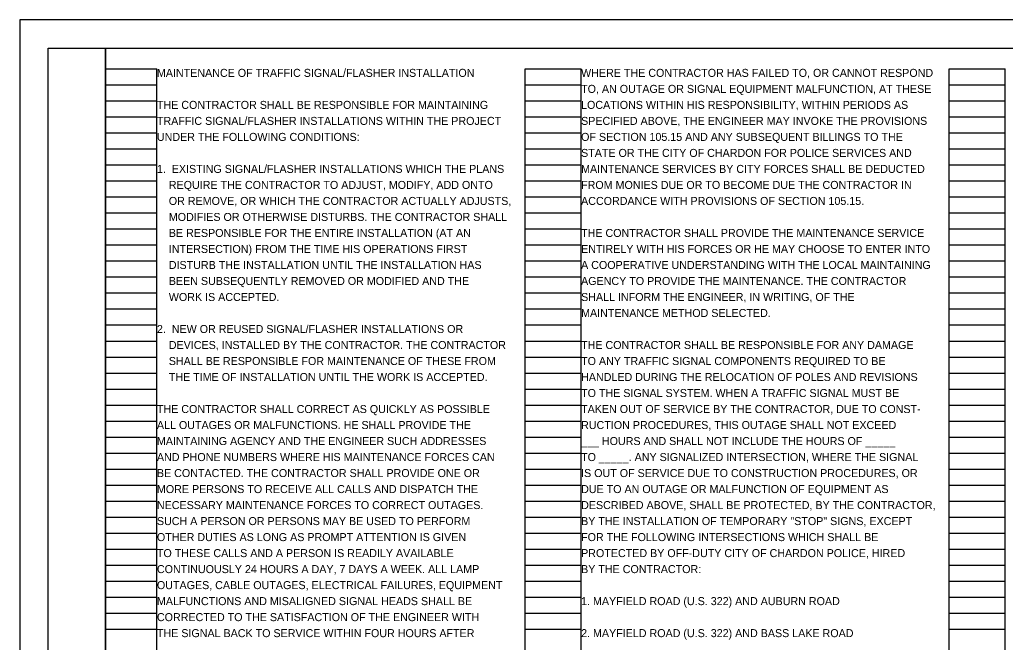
# Model space of a CAD drawing. Extents: x 0 to 63.3, y -2.5 to 22.
# Drawn here: x 0 to 17.24, y 11.11 to 22 of the extents above; entities that cross this region are included whole.
import ezdxf

# ---------------------------------------------------------------- set-up
doc = ezdxf.new("R2010")
doc.units = 0
for name, color, linetype in [('SH_Border', 7, 'Continuous'), ('SH_Cut_Line', 7, 'Continuous'), ('SH_Data', 7, 'Continuous'), ('SH_Text', 7, 'Continuous')]:
    doc.layers.add(name, color=color, linetype=linetype)

msp = doc.modelspace()

# ---------------------------------------------------------------- linework, layer by layer
at = {"layer": 'SH_Border'}
for points in [[(0.5, 21.5), (1.5, 21.5), (1.5, 0.5), (0.5, 0.5)], [(1.5, 21.5), (33.5, 21.5), (33.5, 0.5), (1.5, 0.5)]]:
    msp.add_lwpolyline(points, close=True, dxfattribs=at)
at = {"layer": 'SH_Cut_Line'}
msp.add_lwpolyline([(0, 0), (34, 0), (34, 22), (0, 22)], close=True, dxfattribs=at)
at = {"layer": 'SH_Data'}
for p, q in [((1.5, 0.98), (1.5, 21.14)), ((1.5, 21.14), (2.4, 21.14)), ((2.4, 0.98), (2.4, 21.14)), ((8.84, 0.98), (8.84, 21.14)), ((8.84, 21.14), (9.82, 21.14)), ((9.82, 0.98), (9.82, 21.14)), ((16.26, 0.98), (16.26, 21.14)), ((16.26, 21.14), (17.24, 21.14)), ((17.24, 0.98), (17.24, 21.14)), ((1.5, 20.86), (2.4, 20.86)), ((8.84, 20.86), (9.82, 20.86)), ((16.26, 20.86), (17.24, 20.86)), ((1.5, 20.58), (2.4, 20.58)), ((8.84, 20.58), (9.82, 20.58)), ((16.26, 20.58), (17.24, 20.58)), ((1.5, 20.3), (2.4, 20.3)), ((8.84, 20.3), (9.82, 20.3)), ((16.26, 20.3), (17.24, 20.3)), ((1.5, 20.02), (2.4, 20.02)), ((8.84, 20.02), (9.82, 20.02)), ((16.26, 20.02), (17.24, 20.02)), ((1.5, 19.74), (2.4, 19.74)), ((8.84, 19.74), (9.82, 19.74)), ((16.26, 19.74), (17.24, 19.74)), ((1.5, 19.46), (2.4, 19.46)), ((8.84, 19.46), (9.82, 19.46)), ((16.26, 19.46), (17.24, 19.46)), ((1.5, 19.18), (2.4, 19.18)), ((8.84, 19.18), (9.82, 19.18)), ((16.26, 19.18), (17.24, 19.18)), ((1.5, 18.9), (2.4, 18.9)), ((8.84, 18.9), (9.82, 18.9)), ((16.26, 18.9), (17.24, 18.9)), ((1.5, 18.62), (2.4, 18.62)), ((8.84, 18.62), (9.82, 18.62)), ((16.26, 18.62), (17.24, 18.62)), ((1.5, 18.34), (2.4, 18.34)), ((8.84, 18.34), (9.82, 18.34)), ((16.26, 18.34), (17.24, 18.34)), ((1.5, 18.06), (2.4, 18.06)), ((8.84, 18.06), (9.82, 18.06)), ((16.26, 18.06), (17.24, 18.06)), ((1.5, 17.78), (2.4, 17.78)), ((8.84, 17.78), (9.82, 17.78)), ((16.26, 17.78), (17.24, 17.78)), ((1.5, 17.5), (2.4, 17.5)), ((8.84, 17.5), (9.82, 17.5)), ((16.26, 17.5), (17.24, 17.5)), ((1.5, 17.22), (2.4, 17.22)), ((8.84, 17.22), (9.82, 17.22)), ((16.26, 17.22), (17.24, 17.22)), ((1.5, 16.94), (2.4, 16.94)), ((8.84, 16.94), (9.82, 16.94)), ((16.26, 16.94), (17.24, 16.94)), ((1.5, 16.66), (2.4, 16.66)), ((8.84, 16.66), (9.82, 16.66)), ((16.26, 16.66), (17.24, 16.66)), ((1.5, 16.38), (2.4, 16.38)), ((8.84, 16.38), (9.82, 16.38)), ((16.26, 16.38), (17.24, 16.38)), ((1.5, 16.1), (2.4, 16.1)), ((8.84, 16.1), (9.82, 16.1)), ((16.26, 16.1), (17.24, 16.1)), ((1.5, 15.82), (2.4, 15.82)), ((8.84, 15.82), (9.82, 15.82)), ((16.26, 15.82), (17.24, 15.82)), ((1.5, 15.54), (2.4, 15.54)), ((8.84, 15.54), (9.82, 15.54)), ((16.26, 15.54), (17.24, 15.54)), ((1.5, 15.26), (2.4, 15.26)), ((8.84, 15.26), (9.82, 15.26)), ((16.26, 15.26), (17.24, 15.26)), ((1.5, 14.98), (2.4, 14.98)), ((8.84, 14.98), (9.82, 14.98)), ((16.26, 14.98), (17.24, 14.98)), ((1.5, 14.7), (2.4, 14.7)), ((8.84, 14.7), (9.82, 14.7)), ((16.26, 14.7), (17.24, 14.7)), ((1.5, 14.42), (2.4, 14.42)), ((8.84, 14.42), (9.82, 14.42)), ((16.26, 14.42), (17.24, 14.42)), ((1.5, 14.14), (2.4, 14.14)), ((8.84, 14.14), (9.82, 14.14)), ((16.26, 14.14), (17.24, 14.14)), ((1.5, 13.86), (2.4, 13.86)), ((8.84, 13.86), (9.82, 13.86)), ((16.26, 13.86), (17.24, 13.86)), ((1.5, 13.58), (2.4, 13.58)), ((8.84, 13.58), (9.82, 13.58)), ((16.26, 13.58), (17.24, 13.58)), ((1.5, 13.3), (2.4, 13.3)), ((8.84, 13.3), (9.82, 13.3)), ((16.26, 13.3), (17.24, 13.3)), ((1.5, 13.02), (2.4, 13.02)), ((8.84, 13.02), (9.82, 13.02)), ((16.26, 13.02), (17.24, 13.02)), ((1.5, 12.74), (2.4, 12.74)), ((8.84, 12.74), (9.82, 12.74)), ((16.26, 12.74), (17.24, 12.74)), ((1.5, 12.46), (2.4, 12.46)), ((8.84, 12.46), (9.82, 12.46)), ((16.26, 12.46), (17.24, 12.46)), ((1.5, 12.18), (2.4, 12.18)), ((8.84, 12.18), (9.82, 12.18)), ((16.26, 12.18), (17.24, 12.18)), ((1.5, 11.9), (2.4, 11.9)), ((8.84, 11.9), (9.82, 11.9)), ((16.26, 11.9), (17.24, 11.9)), ((1.5, 11.62), (2.4, 11.62)), ((8.84, 11.62), (9.82, 11.62)), ((16.26, 11.62), (17.24, 11.62)), ((1.5, 11.34), (2.4, 11.34)), ((8.84, 11.34), (9.82, 11.34)), ((16.26, 11.34), (17.24, 11.34))]:
    msp.add_line(p, q, dxfattribs=at)

# ---------------------------------------------------------------- texts
at = {"layer": 'SH_Text'}
for s, p in [('MAINTENANCE OF TRAFFIC SIGNAL/FLASHER INSTALLATION', (2.4, 21)), ('WHERE THE CONTRACTOR HAS FAILED TO, OR CANNOT RESPOND', (9.82, 21)), ('TO, AN OUTAGE OR SIGNAL EQUIPMENT MALFUNCTION, AT THESE', (9.82, 20.72)), ('THE CONTRACTOR SHALL BE RESPONSIBLE FOR MAINTAINING', (2.4, 20.44)), ('LOCATIONS WITHIN HIS RESPONSIBILITY, WITHIN PERIODS AS', (9.82, 20.44)), ('TRAFFIC SIGNAL/FLASHER INSTALLATIONS WITHIN THE PROJECT', (2.4, 20.16)), ('SPECIFIED ABOVE, THE ENGINEER MAY INVOKE THE PROVISIONS', (9.82, 20.16)), ('UNDER THE FOLLOWING CONDITIONS:', (2.4, 19.88)), ('OF SECTION 105.15 AND ANY SUBSEQUENT BILLINGS TO THE', (9.82, 19.88)), ('STATE OR THE CITY OF CHARDON FOR POLICE SERVICES AND', (9.82, 19.6)), ('1.  EXISTING SIGNAL/FLASHER INSTALLATIONS WHICH THE PLANS', (2.4, 19.32)), ('MAINTENANCE SERVICES BY CITY FORCES SHALL BE DEDUCTED', (9.82, 19.32)), ('    REQUIRE THE CONTRACTOR TO ADJUST, MODIFY, ADD ONTO', (2.4, 19.04)), ('FROM MONIES DUE OR TO BECOME DUE THE CONTRACTOR IN', (9.82, 19.04)), ('    OR REMOVE, OR WHICH THE CONTRACTOR ACTUALLY ADJUSTS,', (2.4, 18.76)), ('ACCORDANCE WITH PROVISIONS OF SECTION 105.15.', (9.82, 18.76)), ('    MODIFIES OR OTHERWISE DISTURBS. THE CONTRACTOR SHALL', (2.4, 18.48)), ('    BE RESPONSIBLE FOR THE ENTIRE INSTALLATION (AT AN', (2.4, 18.2)), ('THE CONTRACTOR SHALL PROVIDE THE MAINTENANCE SERVICE', (9.82, 18.2)), ('    INTERSECTION) FROM THE TIME HIS OPERATIONS FIRST', (2.4, 17.92)), ('ENTIRELY WITH HIS FORCES OR HE MAY CHOOSE TO ENTER INTO', (9.82, 17.92)), ('    DISTURB THE INSTALLATION UNTIL THE INSTALLATION HAS', (2.4, 17.64)), ('A COOPERATIVE UNDERSTANDING WITH THE LOCAL MAINTAINING', (9.82, 17.64)), ('    BEEN SUBSEQUENTLY REMOVED OR MODIFIED AND THE', (2.4, 17.36)), ('AGENCY TO PROVIDE THE MAINTENANCE. THE CONTRACTOR', (9.82, 17.36)), ('    WORK IS ACCEPTED.', (2.4, 17.08)), ('SHALL INFORM THE ENGINEER, IN WRITING, OF THE', (9.82, 17.08)), ('MAINTENANCE METHOD SELECTED.', (9.82, 16.8)), ('2.  NEW OR REUSED SIGNAL/FLASHER INSTALLATIONS OR', (2.4, 16.52)), ('    DEVICES, INSTALLED BY THE CONTRACTOR. THE CONTRACTOR', (2.4, 16.24)), ('THE CONTRACTOR SHALL BE RESPONSIBLE FOR ANY DAMAGE', (9.82, 16.24)), ('    SHALL BE RESPONSIBLE FOR MAINTENANCE OF THESE FROM', (2.4, 15.96)), ('TO ANY TRAFFIC SIGNAL COMPONENTS REQUIRED TO BE', (9.82, 15.96)), ('    THE TIME OF INSTALLATION UNTIL THE WORK IS ACCEPTED.', (2.4, 15.68)), ('HANDLED DURING THE RELOCATION OF POLES AND REVISIONS', (9.82, 15.68)), ('TO THE SIGNAL SYSTEM. WHEN A TRAFFIC SIGNAL MUST BE', (9.82, 15.4)), ('THE CONTRACTOR SHALL CORRECT AS QUICKLY AS POSSIBLE', (2.4, 15.12)), ('TAKEN OUT OF SERVICE BY THE CONTRACTOR, DUE TO CONST-', (9.82, 15.12)), ('ALL OUTAGES OR MALFUNCTIONS. HE SHALL PROVIDE THE', (2.4, 14.84)), ('RUCTION PROCEDURES, THIS OUTAGE SHALL NOT EXCEED', (9.82, 14.84)), ('MAINTAINING AGENCY AND THE ENGINEER SUCH ADDRESSES', (2.4, 14.56)), ('___ HOURS AND SHALL NOT INCLUDE THE HOURS OF _____', (9.82, 14.56)), ('AND PHONE NUMBERS WHERE HIS MAINTENANCE FORCES CAN', (2.4, 14.28)), ('TO _____. ANY SIGNALIZED INTERSECTION, WHERE THE SIGNAL', (9.82, 14.28)), ('BE CONTACTED. THE CONTRACTOR SHALL PROVIDE ONE OR', (2.4, 14)), ('IS OUT OF SERVICE DUE TO CONSTRUCTION PROCEDURES, OR', (9.82, 14)), ('MORE PERSONS TO RECEIVE ALL CALLS AND DISPATCH THE', (2.4, 13.72)), ('DUE TO AN OUTAGE OR MALFUNCTION OF EQUIPMENT AS', (9.82, 13.72)), ('NECESSARY MAINTENANCE FORCES TO CORRECT OUTAGES.', (2.4, 13.44)), ('DESCRIBED ABOVE, SHALL BE PROTECTED, BY THE CONTRACTOR,', (9.82, 13.44)), ('SUCH A PERSON OR PERSONS MAY BE USED TO PERFORM', (2.4, 13.16)), ('BY THE INSTALLATION OF TEMPORARY "STOP" SIGNS, EXCEPT', (9.82, 13.16)), ('OTHER DUTIES AS LONG AS PROMPT ATTENTION IS GIVEN', (2.4, 12.88)), ('FOR THE FOLLOWING INTERSECTIONS WHICH SHALL BE', (9.82, 12.88)), ('TO THESE CALLS AND A PERSON IS READILY AVAILABLE', (2.4, 12.6)), ('PROTECTED BY OFF-DUTY CITY OF CHARDON POLICE, HIRED', (9.82, 12.6)), ('CONTINUOUSLY 24 HOURS A DAY, 7 DAYS A WEEK. ALL LAMP', (2.4, 12.32)), ('BY THE CONTRACTOR:', (9.82, 12.32)), ('OUTAGES, CABLE OUTAGES, ELECTRICAL FAILURES, EQUIPMENT', (2.4, 12.04)), ('MALFUNCTIONS AND MISALIGNED SIGNAL HEADS SHALL BE', (2.4, 11.76)), ('1. MAYFIELD ROAD (U.S. 322) AND AUBURN ROAD', (9.82, 11.76)), ('CORRECTED TO THE SATISFACTION OF THE ENGINEER WITH', (2.4, 11.48)), ('THE SIGNAL BACK TO SERVICE WITHIN FOUR HOURS AFTER', (2.4, 11.2)), ('2. MAYFIELD ROAD (U.S. 322) AND BASS LAKE ROAD', (9.82, 11.2))]:
    msp.add_text(s, height=0.14, dxfattribs=at).set_placement(p)

doc.saveas('drawing.dxf')
